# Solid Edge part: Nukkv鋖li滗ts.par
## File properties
Author: Türk
Template: Iso Part.par
Last saved by: Türk
Revision: 14
Application: Solid Edge
Accuracy: 0,990
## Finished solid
Body 1: solid body, 37 faces, 86 edges, 52 vertices.
  Faces by surface: plane 18, cylinder 17, blend 2
  Edges by curve: circle 49, line 32, intersection 4, curve on surface 1
Bounding box of the edges (mm; curved faces can reach further): 52.747 x 46.000 x 16.600, from (-49.4984, -23, -17) to (3.2483, 23, -0.4).
Cylindrical faces by radius (mm): R3 x1, R5 x2, R7.375 x2, R8 x2, R10 x6, R26.1667 x2, R31.1667 x2
Planar faces by outward normal: +y 5, -y 5, oblique 8
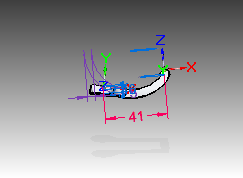
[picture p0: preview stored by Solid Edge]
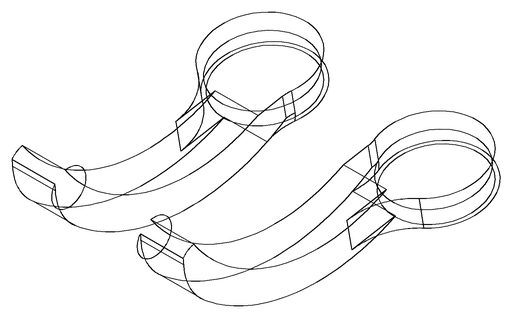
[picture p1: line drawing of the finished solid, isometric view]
